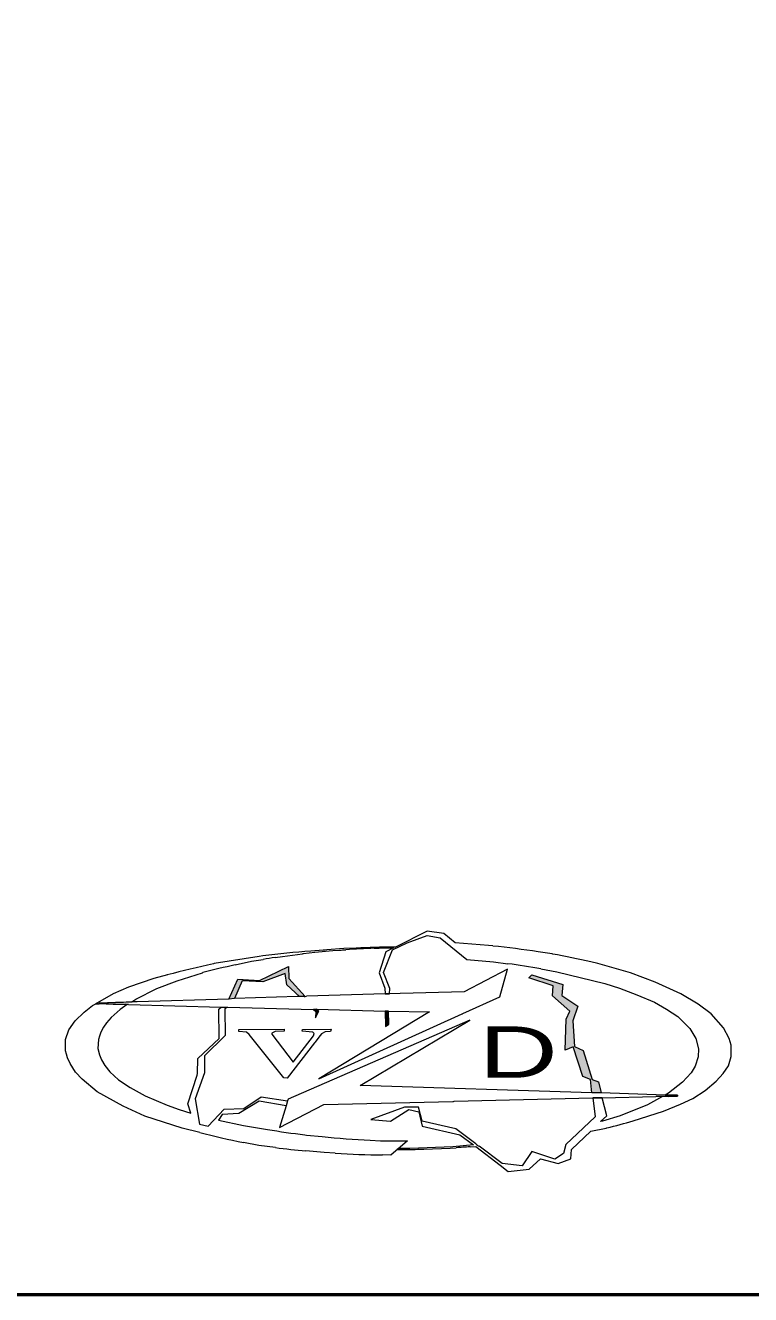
# Model space of a CAD drawing. Extents: x 312000 to 314820, y 245421 to 253140.
# Drawn here: x 314180.9 to 314400.8, y 245420.8 to 245805.3 of the extents above; entities that cross this region are included whole.
import ezdxf
from ezdxf.enums import TextEntityAlignment as Align

# ---------------------------------------------------------------- set-up
doc = ezdxf.new("R2010")
doc.units = 0
doc.header["$LTSCALE"] = 10
doc.layers.add('60', color=7, linetype='Continuous', lineweight=53)
doc.layers.add('61', color=7, linetype='Continuous', lineweight=13)

msp = doc.modelspace()

# ---------------------------------------------------------------- hatches: boundary and pattern name
at = {"layer": '61'}
for points in [[(314244.26, 245510.45), (314242.56, 245510.31), (314245.33, 245516.37), (314251.93, 245515.98), (314260.71, 245520.15), (314260.8, 245516.51), (314265.75, 245511.13), (314264.01, 245511.08), (314260.13, 245514.67), (314259.69, 245518.06), (314252.9, 245515.49), (314246.64, 245515.79)], [(314355.42, 245481.89), (314352.59, 245481.89), (314352.18, 245485.9), (314349.88, 245486.84), (314346.93, 245495.8), (314344.52, 245494.85), (314344.87, 245504.22), (314345.93, 245506.64), (314340.68, 245511.29), (314340.92, 245514.36), (314333.49, 245516.77), (314334.43, 245517.6), (314343.87, 245514.71), (314343.57, 245511.35), (314348.41, 245508.11), (314346.87, 245503.69), (314347.41, 245495.91), (314350, 245494.74), (314352.71, 245485.96), (314354.66, 245485.25)], [(314269.28, 245507.29), (314268.23, 245507.17), (314268.97, 245506.57), (314268.91, 245504.66), (314269.85, 245506.62)], [(314291.01, 245506.65), (314289.99, 245506.65), (314290.11, 245502.02), (314291.05, 245502.69)]]:
    msp.add_hatch(color=256, dxfattribs=at).paths.add_polyline_path(points)

# ---------------------------------------------------------------- linework, layer by layer
at = {"layer": '60'}
msp.add_lwpolyline([(314819.64, 253140.4), (312000.01, 253140.4), (312000.01, 245420.78), (314819.64, 245420.78)], close=True, dxfattribs=at)
at = {"layer": '61'}
for p, q in [((314271.22, 245525.12), (314267.45, 245524.83)), ((314277.83, 245525.23), (314278.05, 245525.24)), ((314265.41, 245511.12), (314264.65, 245511.1)), ((314285.46, 245467.53), (314288.53, 245467.37))]:
    msp.add_line(p, q, dxfattribs=at)
for points in [[(314286.68, 245525.68), (314288.18, 245525.74), (314292.47, 245525.83), (314290.19, 245524.65), (314288.13, 245518.3), (314289.93, 245513.56), (314289.97, 245511.86), (314291.33, 245511.86), (314291.38, 245513.52), (314289.45, 245518.38), (314292.21, 245525.26), (314296.68, 245527.32), (314302.67, 245529.6), (314306.66, 245528.9), (314314.75, 245522.28), (314322.83, 245521.62), (314327.18, 245521.01)], [(314322.59, 245526.39), (314321.31, 245526.52), (314311.23, 245527.3), (314307.78, 245530.18), (314302.74, 245530.86), (314293.12, 245526.05), (314292.45, 245526.05)], [(314252.92, 245523.38), (314251.76, 245523.23), (314238.16, 245521.04), (314237.92, 245520.99)], [(314256.68, 245522.91), (314258.87, 245523.24), (314264.94, 245524.06)], [(314265.25, 245524.1), (314268.67, 245524.56), (314274.1, 245525), (314276.19, 245525.12)], [(314281.23, 245525.75), (314277.43, 245525.58), (314272.26, 245525.2)], [(314340.8, 245523.95), (314340.64, 245523.98), (314336.38, 245524.62)], [(314244.56, 245520.66), (314249.51, 245521.76), (314252.99, 245522.33)], [(314365.16, 245473.41), (314365.18, 245473.41), (314374.37, 245476.31), (314379.52, 245478.49), (314383.21, 245480.22), (314386.96, 245482.63), (314390.35, 245485.48), (314392.48, 245487.77), (314394.05, 245490.12), (314394.89, 245492.9), (314394.83, 245496.31), (314394.22, 245498.38), (314392.54, 245501.57), (314388.79, 245505.82), (314384.87, 245508.73), (314379.63, 245511.92), (314371.85, 245515.44), (314364.31, 245518.22), (314354.48, 245521.07), (314352.36, 245521.55)], [(314223.95, 245517.63), (314219.84, 245516.55), (314212.14, 245513.9), (314207.54, 245511.92), (314202.11, 245508.81), (314203.28, 245508.91), (314203.28, 245509.05), (314213.15, 245509.45), (314214.44, 245510.32), (314220.75, 245513.52), (314226.96, 245515.84), (314234.63, 245518.3), (314234.68, 245518.31)], [(314313.54, 245505.89), (314324.78, 245510.97), (314327.02, 245519.37), (314313.95, 245512.46), (314290.65, 245511.86), (314289.97, 245511.86), (314266.1, 245511.14)], [(314337.21, 245519.44), (314342.05, 245518.6), (314356.55, 245515.01), (314361.02, 245513.61), (314366.28, 245511.59), (314371.63, 245509.32), (314375.31, 245507.21), (314378.68, 245505.02), (314382.34, 245501.41), (314384.14, 245498.41), (314384.97, 245495.19), (314384.82, 245492.8), (314383.92, 245490.03), (314382.79, 245487.93), (314380.17, 245485.16), (314375.9, 245481.79), (314374.84, 245481.2), (314378.6, 245481.18), (314378.6, 245480.86), (314374.01, 245480.8), (314369.51, 245478.28), (314361.22, 245474.95), (314355.82, 245473.35), (314355.3, 245473.23), (314357.2, 245474.89), (314355.76, 245480.34), (314352.89, 245480.4), (314353.64, 245474.66), (314344.77, 245466.29), (314344.08, 245463.48), (314341.44, 245461.82), (314334.44, 245464.11), (314331.49, 245459.76), (314325.47, 245460.45), (314318.45, 245465.7)], [(314233.79, 245469.86), (314228.4, 245471.21), (314217.16, 245474.83), (314210.54, 245477.83), (314202.67, 245482.2), (314198.17, 245486.06), (314196.14, 245488.21), (314194.49, 245490.77), (314193.64, 245492.47), (314193.37, 245493.59), (314193.11, 245494.6), (314193.11, 245498.11), (314194.07, 245500.99), (314195.98, 245503.7), (314198.7, 245506.36), (314201.31, 245508.33), (314202.11, 245508.81), (314203.33, 245508.92), (314211.75, 245508.71), (314209.62, 245507.16), (314206.95, 245504.77), (314205.46, 245503.12), (314204.61, 245501.79), (314203.81, 245500.3), (314203.39, 245499.07), (314203.07, 245498.06), (314202.91, 245495.35), (314203.37, 245493.38), (314204.01, 245491.89), (314205.03, 245490.18), (314206.52, 245488.27), (314209.18, 245485.87), (314212.7, 245483.48), (314217.26, 245480.98), (314223.86, 245478.21), (314227.54, 245476.88), (314231.11, 245475.77), (314230.17, 245478.55), (314232.99, 245487.25), (314233.14, 245487.81), (314233.18, 245492.35), (314239.62, 245498.4), (314239.56, 245507.25), (314240.29, 245507.9), (314242.15, 245507.9), (314241.41, 245507.34), (314241.47, 245499.26), (314235.23, 245493.1), (314235.23, 245488), (314232.36, 245480.11), (314233.73, 245472.46), (314236.29, 245471.78), (314241.2, 245477), (314247.18, 245477.19), (314252.41, 245480.74), (314260.39, 245479.52), (314260, 245478), (314251.83, 245479.4), (314245.58, 245475.65), (314240.57, 245475.35), (314239.5, 245473.62), (314247.06, 245471.96), (314254.29, 245470.79)], [(314211.48, 245509.38), (314208.21, 245509.25), (314203.28, 245509.05), (314203.33, 245508.92), (314207.54, 245508.81), (314211.31, 245508.72)], [(314212.18, 245508.69), (314240.29, 245507.9), (314242.15, 245507.9), (314268.23, 245507.17), (314269.28, 245507.29), (314289.99, 245506.65), (314291.01, 245506.65), (314303.45, 245506.4), (314269.85, 245486.16), (314313.34, 245505.8)], [(314263.36, 245511.06), (314244.26, 245510.45), (314242.56, 245510.31), (314214.81, 245509.49)], [(314245.58, 245500.49), (314245.58, 245501.11), (314259.37, 245501.18), (314259.37, 245500.55), (314256.63, 245500.49), (314255.61, 245499.98), (314255.66, 245499.64), (314262.05, 245491.15), (314268.21, 245499.18), (314268.44, 245499.92), (314268.1, 245500.32), (314264.85, 245500.55), (314264.96, 245501.12), (314273.57, 245501.18), (314273.46, 245500.49), (314271.8, 245500.43), (314270.66, 245499.75), (314269.86, 245498.73), (314268.74, 245497.28)], [(314268.6, 245497.1), (314260.23, 245486.36), (314259.26, 245486.42), (314248.71, 245499.58), (314247.91, 245500.32), (314245.58, 245500.49)], [(314315.7, 245503.96), (314260.57, 245479.98), (314260.39, 245479.52), (314260, 245478), (314257.99, 245471.43), (314271.34, 245478.37), (314310.54, 245479.32)], [(314375.97, 245480.83), (314378.6, 245480.86), (314378.6, 245481.18), (314374.84, 245481.2), (314355.42, 245481.89), (314352.59, 245481.89), (314282.45, 245484.1), (314315.7, 245503.96)], [(314295.83, 245477.6), (314285.68, 245473.81), (314291.61, 245473.32), (314297.12, 245476.83), (314300.14, 245476.12), (314301.17, 245471.77), (314312.58, 245469.23), (314316.78, 245466.14), (314310.52, 245465.51), (314297.44, 245465.03), (314293.99, 245465.01), (314293.62, 245464.69), (314294.75, 245464.7)], [(314317.45, 245466.45), (314311.41, 245471), (314301.22, 245473.3), (314300.13, 245477.54), (314295.83, 245477.6)], [(314310.91, 245479.33), (314352.89, 245480.4), (314355.76, 245480.34), (314372.04, 245480.75)], [(314315.72, 245465.54), (314317.45, 245465.64), (314324.88, 245460.04), (314327.23, 245458.09), (314333.66, 245458.81), (314337.05, 245461.89), (314342.43, 245460.49), (314346.23, 245461.95), (314346.46, 245464.69), (314352.3, 245470.33), (314357.01, 245471.23), (314357.22, 245471.28)], [(314256.73, 245465.3), (314251.66, 245465.92), (314247.05, 245466.86)], [(314265.6, 245469.17), (314266.15, 245469.1), (314270.92, 245468.63)], [(314288.53, 245467.37), (314296.71, 245467.35), (314291.72, 245463.05), (314289.22, 245463.08)], [(314274.87, 245463.6), (314271.48, 245463.8), (314265.96, 245464.3)], [(314301.66, 245464.86), (314309.69, 245465.13), (314311.47, 245465.26)]]:
    msp.add_lwpolyline(points, dxfattribs=at)
for points in [[(314244.26, 245510.45), (314242.56, 245510.31), (314245.33, 245516.37), (314251.93, 245515.98), (314260.71, 245520.15), (314260.8, 245516.51), (314265.75, 245511.13), (314264.01, 245511.08), (314260.13, 245514.67), (314259.69, 245518.06), (314252.9, 245515.49), (314246.64, 245515.79)], [(314355.42, 245481.89), (314352.59, 245481.89), (314352.18, 245485.9), (314349.88, 245486.84), (314346.93, 245495.8), (314344.52, 245494.85), (314344.87, 245504.22), (314345.93, 245506.64), (314340.68, 245511.29), (314340.92, 245514.36), (314333.49, 245516.77), (314334.43, 245517.6), (314343.87, 245514.71), (314343.57, 245511.35), (314348.41, 245508.11), (314346.87, 245503.69), (314347.41, 245495.91), (314350, 245494.74), (314352.71, 245485.96), (314354.66, 245485.25)], [(314269.28, 245507.29), (314268.23, 245507.17), (314268.97, 245506.57), (314268.91, 245504.66), (314269.85, 245506.62)], [(314291.01, 245506.65), (314289.99, 245506.65), (314290.11, 245502.02), (314291.05, 245502.69)]]:
    msp.add_lwpolyline(points, close=True, dxfattribs=at)
for centre, start, end in [((314291.24, 245214.71), 94.3875, 97.0766), ((314223.71, 245832.35), 277.616, 277.6734), ((314295.01, 245215), 94.1949, 94.3875), ((314257.5, 245835.6), 273.4459, 273.7492), ((314298.39, 245214.87), 92.1565, 93.7492), ((314295.03, 245215.02), 90.4758, 92.5431), ((314290.04, 245217.05), 81.4326, 83.993), ((314283.42, 245218.25), 77.1951, 79.3709), ((314303.5, 245216.94), 102.1714, 104.8197), ((314311.7, 245216.96), 102.4671, 104.3377), ((314303.44, 245215.41), 98.6469, 99.3347), ((314284.03, 245212.98), 80.1552, 82.0251), ((314203.45, 245197.78), 88.3913, 88.5507), ((314223.89, 245198.59), 91.6733, 92.2865), ((314273.28, 245200.18), 91.5901, 91.8283), ((314256.78, 245822.04), 271.5901, 271.7162), ((314185.34, 245789.28), 294.3, 294.3419), ((314023.28, 245688.32), 322.0647, 322.1065), ((314302.99, 245790.27), 271.3916, 271.4597), ((314379.86, 245169.81), 90.7157, 91.4403), ((314280.88, 245772.81), 284.2068, 285.7221), ((314309.18, 245771.63), 255.9728, 258.4773), ((314304.01, 245777.83), 260.8019, 262.9067), ((314301.55, 245778.16), 264.3493, 267.0359), ((314504.69, 245714.82), 232.988, 233.2185), ((314294.55, 245774.03), 263.0161, 264.727), ((314293.23, 245774.09), 266.6159, 269.2612), ((314291.07, 245775.72), 270.6772, 271.9512), ((314333.71, 245155.02), 93.3156, 94.1004)]:
    msp.add_arc(centre, 311.04, start, end, dxfattribs=at)

# ---------------------------------------------------------------- texts
at = {"layer": '61', "width": 1.6}
msp.add_text('D', height=15.55, dxfattribs=at).set_placement((314330.31, 245486.49), align=Align.CENTER)

doc.saveas('drawing.dxf')
